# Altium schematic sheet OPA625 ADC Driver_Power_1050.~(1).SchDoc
size 558 x 431 mm; Date: Not shown in title block; ApprovedBy: Not shown in title block; CheckedBy: Not shown in title block; Author: Not shown in title block; CompanyName: Not shown in title block; Engineer: Not shown in title block; Organization: Not shown in title block; Address1: Not shown in title block; Address2: Not shown in title block; Address3: Not shown in title block; Address4: Not shown in title block; DocumentNumber: 2; Revision: Use project parameter SCH_Rev; SheetNumber: 2; SheetTotal: 8; PageSetup: Record=PageOptions¦CenterHorizontal=True¦CenterVertical=True¦PrintScale=1.00¦XCorrection=1.00¦YCorrection=1.00¦PrintKind=0¦BorderSize=5000000¦LeftOffset=0¦BottomOffset=0¦Orientation=2¦PaperLength=1000¦PaperWidth=1000¦Scale=100¦PaperSource=15¦PrintQuality=600¦MediaType=1¦DitherType=10¦PaperKind=Letter¦PrintScaleMode=1
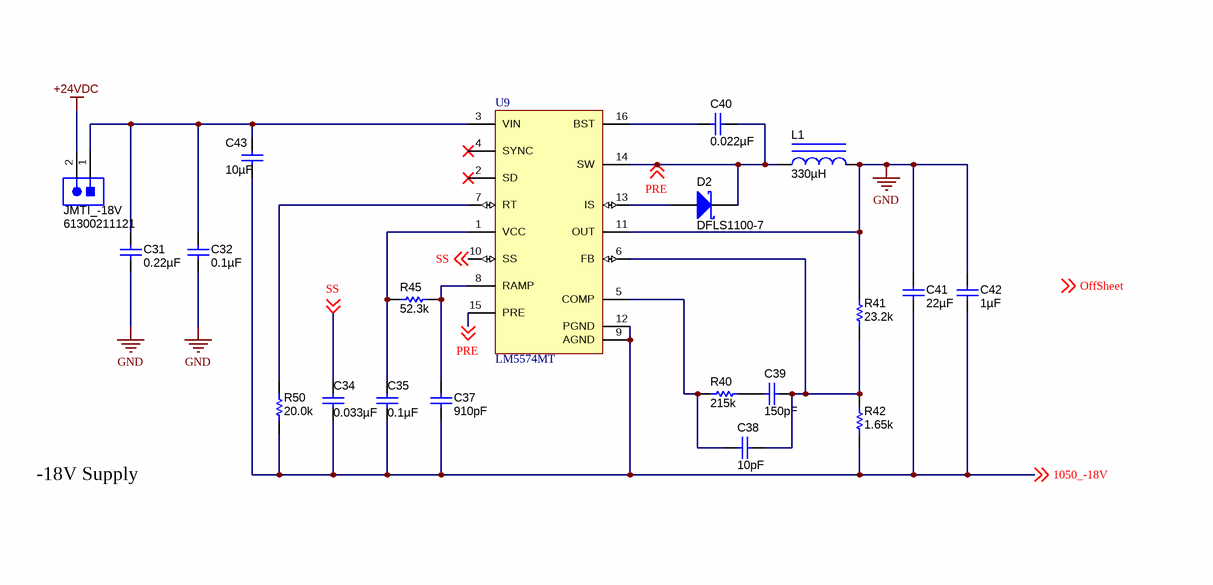
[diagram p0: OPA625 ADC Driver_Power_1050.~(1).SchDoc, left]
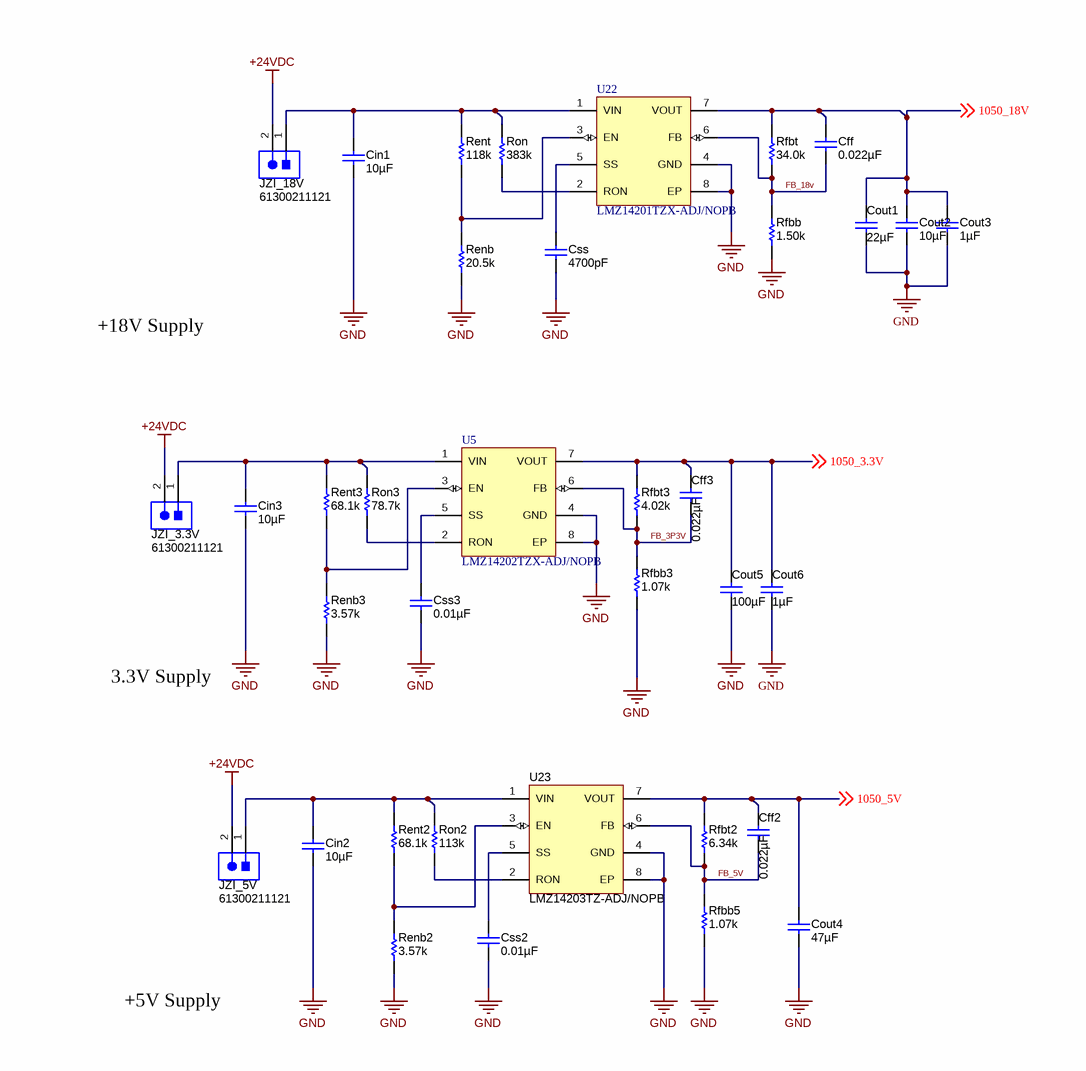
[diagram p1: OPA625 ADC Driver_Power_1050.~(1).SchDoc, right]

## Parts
C31  ValueDisplayed: 0.22µF  [0603]  (hidden comment: GCM188R71H224KA64D)
C32  ValueDisplayed: 0.1µF  [0603]  (hidden comment: C1608X7R1H104K080AA)
C34  ValueDisplayed: 0.033µF  [0603]  (hidden comment: GRM188R71H333KA61D)
C35  ValueDisplayed: 0.1µF  [0603]  (hidden comment: C1608X7R1H104K080AA)
C37  ValueDisplayed: 910pF  [0603]  (hidden comment: C0603C911J5GACTU)
C38  ValueDisplayed: 10pF  [0603]  (hidden comment: CGA3E2C0G1H100D080AA)
C39  ValueDisplayed: 150pF  [0603]  (hidden comment: GRM1885C1H151JA01D)
C40  ValueDisplayed: 0.022µF  [0603]  (hidden comment: GRM188R71H223KA01D)
C41  ValueDisplayed: 22µF  [0805_HV]  (hidden comment: C2012X5R1V226M125AC)
C42  ValueDisplayed: 1µF  [0805_HV]  (hidden comment: C2012X7S2A105K125AB)
C43  ValueDisplayed: 10µF  [1210_280]  (hidden comment: UMK325AB7106KM-T)
Cff  ValueDisplayed: 0.022µF  [0603]  (hidden comment: C1608X7R2A223K080AA)
Cff2  ValueDisplayed: 0.022µF  [0805_HV]  (hidden comment: 08055C223KAT2A)
Cff3  ValueDisplayed: 0.022µF  [0805_HV]  (hidden comment: 08055C223KAT2A)
Cin1  ValueDisplayed: 10µF  [1210_280]  (hidden comment: UMK325AB7106KM-T)
Cin2  ValueDisplayed: 10µF  [1210_280]  (hidden comment: UMK325AB7106KM-T)
Cin3  ValueDisplayed: 10µF  [1210_280]  (hidden comment: UMK325AB7106KM-T)
Cout1  ValueDisplayed: 22µF  [0805_HV]  (hidden comment: C2012JB1V226M125AC)
Cout2  ValueDisplayed: 10µF  [1210_280]  (hidden comment: UMK325AB7106KM-T)
Cout3  ValueDisplayed: 1µF  [0805_HV]  (hidden comment: C2012X7S2A105K125AB)
Cout4  ValueDisplayed: 47µF  [1206_190]  (hidden comment: C3216X5R1E476M160AC)
Cout5  ValueDisplayed: 100µF  [1210_280]  (hidden comment: C3225X6S0J107M250AC)
Cout6  ValueDisplayed: 1µF  [0603]  (hidden comment: C0603C105K3RACTU)
Css  ValueDisplayed: 4700pF  [0603]  (hidden comment: CGA3E2X7R2A472K080AA)
Css2  ValueDisplayed: 0.01µF  [0603]  (hidden comment: GRM188R70J103KA01D)
Css3  ValueDisplayed: 0.01µF  [0603]  (hidden comment: GRM188R70J103KA01D)
D2  DFLS1100-7  [PowerDI123]
JMTI_-18V  61300211121  [WURTH_61300211121]
JZI_3.3V  61300211121  [WURTH_61300211121]
JZI_5V  61300211121  [WURTH_61300211121]
JZI_18V  61300211121  [WURTH_61300211121]
L1  ValueDisplayed: 330µH  [DR73]  (hidden comment: DR73-331-R)
R40  ValueDisplayed: 215k  [0603]  (hidden comment: RT0603BRD07215KL)
R41  ValueDisplayed: 23.2k  [0603]  (hidden comment: RG1608P-2322-B-T5)
R42  ValueDisplayed: 1.65k  [0603]  (hidden comment: RG1608P-1651-B-T5)
R45  ValueDisplayed: 52.3k  [0603]  (hidden comment: RT0603BRD0752K3L)
R50  ValueDisplayed: 20.0k  [0603]  (hidden comment: RG1608P-203-B-T5)
Renb  ValueDisplayed: 20.5k  [0805_HV]  (hidden comment: CRCW080520K5FKEA)
Renb2  ValueDisplayed: 3.57k  [0603]  (hidden comment: RG1608P-3571-B-T5)
Renb3  ValueDisplayed: 3.57k  [0603]  (hidden comment: RG1608P-3571-B-T5)
Rent  value 118k  [0805_HV]  (hidden comment: RT0805BRD07118KL)
Rent2  ValueDisplayed: 68.1k  [0603]  (hidden comment: RT0603BRD0768K1L)
Rent3  ValueDisplayed: 68.1k  [0603]  (hidden comment: RT0603BRD0768K1L)
Rfbb  ValueDisplayed: 1.50k  [0603]  (hidden comment: RG1608P-152-B-T5)
Rfbb3  ValueDisplayed: 1.07k  [0805_HV]  (hidden comment: RT0805BRD071K07L)
Rfbb5  ValueDisplayed: 1.07k  [0805_HV]  (hidden comment: RT0805BRD071K07L)
Rfbt  ValueDisplayed: 34.0k  [0603]  (hidden comment: RT0603BRD0734KL)
Rfbt2  ValueDisplayed: 6.34k  [0603]  (hidden comment: CPF0603B6K34E)
Rfbt3  ValueDisplayed: 4.02k  [0603]  (hidden comment: RG1608P-4021-B-T5)
Ron  ValueDisplayed: 383k  [0603]  (hidden comment: RT0603BRD07383KL)
Ron2  ValueDisplayed: 113k  [0603]  (hidden comment: RT0603BRD07113KL)
Ron3  ValueDisplayed: 78.7k  [0603]  (hidden comment: RT0603BRD0778K7L)
U5  LMZ14202TZX-ADJ/NOPB  [TZA07A_V]
U9  LM5574MT  [MTC16_N]
U22  LMZ14201TZX-ADJ/NOPB  [TZA07A_V]
U23  LMZ14203TZ-ADJ/NOPB  [TZA07A_V]

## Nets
+24VDC: JMTI_-18V.2 JZI_3.3V.2 JZI_5V.2 JZI_18V.2
GND: C31.2 C32.2 C41.1 C42.1 Cin1.2 Cin2.2 Cin3.2 Cout1.2 Cout2.2 Cout3.2 Cout4.2 Cout5.2 Cout6.2 Css.1 Css2.2 Css3.2 L1.2 R41.2 Renb.1 Renb2.1 Renb3.1 Rfbb.1 Rfbb3.1 Rfbb5.1 U5.4(GND) U5.8(EP) U9.11(OUT) U22.4(GND) U22.8(EP) U23.4(GND) U23.8(EP)
1050_3.3V: Cff3.1 Cout5.1 Cout6.1 Rfbt3.2 U5.7(VOUT) ; off-sheet 1050_3.3V
1050_5V: Cff2.1 Cout4.1 Rfbt2.2 U23.7(VOUT) ; off-sheet 1050_5V
1050_18V: Cff.1 Cout1.1 Cout2.1 Cout3.1 Rfbt.2 U22.7(VOUT) ; off-sheet 1050_18V
1050_-18V: C34.2 C35.2 C37.2 C41.2 C42.2 C43.2 R42.1 R50.1 U9.9(AGND) U9.12(PGND) ; off-sheet 1050_-18V
FB_3P3V: Cff3.2 Rfbb3.2 Rfbt3.1 U5.6(FB)
FB_5V: Cff2.2 Rfbb5.2 Rfbt2.1 U23.6(FB)
FB_18v: Cff.2 Rfbb.2 Rfbt.1 U22.6(FB)
PRE: C40.1 D2.1(K) L1.1 U9.14(SW) U9.15(PRE) ; off-sheet PRE
SS: C34.1 U9.10(SS) ; off-sheet SS
NetC31_1: C31.1 C32.1 C43.1 JMTI_-18V.1 U9.3(VIN)
NetC35_1: C35.1 R45.1 U9.1(VCC)
NetC37_1: C37.1 R45.2 U9.8(RAMP)
NetC38_1: C38.1 C39.1 R41.1 R42.2 U9.6(FB)
NetC38_2: C38.2 R40.1 U9.5(COMP)
NetC39_2: C39.2 R40.2
NetC40_2: C40.2 U9.16(BST)
NetCin1_1: Cin1.1 JZI_18V.1 Rent.2 Ron.2 U22.1(VIN)
NetCin2_1: Cin2.1 JZI_5V.1 Rent2.2 Ron2.2 U23.1(VIN)
NetCin3_1: Cin3.1 JZI_3.3V.1 Rent3.2 Ron3.2 U5.1(VIN)
NetCss2_1: Css2.1 U23.5(SS)
NetCss3_1: Css3.1 U5.5(SS)
NetCss_2: Css.2 U22.5(SS)
NetD2_2: D2.2(A) U9.13(IS)
NetR50_2: R50.2 U9.7(RT)
NetRenb2_2: Renb2.2 Rent2.1 U23.3(EN)
NetRenb3_2: Renb3.2 Rent3.1 U5.3(EN)
NetRenb_2: Renb.2 Rent.1 U22.3(EN)
NetRon2_1: Ron2.1 U23.2(RON)
NetRon3_1: Ron3.1 U5.2(RON)
NetRon_1: Ron.1 U22.2(RON)

Not connected (* = marked no-connect by the designer): U9 2(SD)* 4(SYNC)*

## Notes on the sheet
- +18V Supply
- -18V Supply
- 3.3V Supply
- +5V Supply
- Labels drawn without touching a wire or pin: OffSheet

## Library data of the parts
C31 = GCM188R71H224KA64D: CAP, CERM, 0.22 µF, 50 V, +/- 10%, X7R, AEC-Q200 Grade 1, 0603; Manufacturer: MuRata; Polarized: N; CompType: Capacitor; Value: 0.22uF; U/M: EA; Cap_F: 0.00000022; Tolerance_%: 10; Value1: Unknown; VDC_V: 50; Value2: 50V; TaMin_C: -55; TaMax_C: 125; SizeArea_mm2: 1.28; SizeAreaWB_mm2: 4.68; SizeX_mm: 1.6; SizeY_mm: 0.8; SizeZ_mm: 1; AEC Category: Q200; AEC Qualified: Y
C32 C35 = C1608X7R1H104K080AA: CAP, CERM, 0.1 µF, 50 V, +/- 10%, X7R, 0603; Manufacturer: TDK; Polarized: N; CompType: Capacitor; Value: 0.1uF; U/M: EA; Cap_F: 0.0000001; Tolerance_%: 10; ESR_ohm: 0.0296; Value1: 0.0296 ohm; VDC_V: 50; Value2: 50V; IRMS_A: 0.97199; TaMin_C: -55; TaMax_C: 125; SizeArea_mm2: 1.28; SizeAreaWB_mm2: 4.68; SizeX_mm: 1.6; SizeY_mm: 0.8; SizeZ_mm: 1; AEC Category: Q200
C34 = GRM188R71H333KA61D: CAP, CERM, 0.033 µF, 50 V, +/- 10%, X7R, 0603; Manufacturer: MuRata; Polarized: N; CompType: Capacitor; Value: 0.033uF; U/M: EA; Cap_F: 0.000000033; Tolerance_%: 10; Value1: Unknown; VDC_V: 50; Value2: 50V; TaMin_C: -55; TaMax_C: 125; SizeArea_mm2: 1.28; SizeAreaWB_mm2: 4.68; SizeX_mm: 1.6; SizeY_mm: 0.8; SizeZ_mm: 1; AEC Category: Q200
C37 = C0603C911J5GACTU: CAP, CERM, 910 pF, 50 V, +/- 5%, C0G/NP0, 0603; Manufacturer: Kemet; Polarized: N; CompType: Capacitor; Value: 910pF; U/M: EA; Cap_F: 0.00000000091; Tolerance_%: 5; Value1: Unknown; VDC_V: 50; Value2: 50V; TaMin_C: -55; TaMax_C: 125; SizeArea_mm2: 1.28; SizeAreaWB_mm2: 4.68; SizeX_mm: 1.6; SizeY_mm: 0.8; SizeZ_mm: 1; AEC Category: Q200
C38 = CGA3E2C0G1H100D080AA: CAP, CERM, 10 pF, 50 V, +/- 5%, C0G/NP0, AEC-Q200 Grade 1, 0603; Manufacturer: TDK; Polarized: N; CompType: Capacitor; Value: 10pF; U/M: EA; Cap_F: 0.00000000001; Tolerance_%: 5; Value1: Unknown; VDC_V: 50; Value2: 50V; TaMin_C: -55; TaMax_C: 125; SizeArea_mm2: 1.28; SizeAreaWB_mm2: 4.68; SizeX_mm: 1.6; SizeY_mm: 0.8; SizeZ_mm: 1; AEC Category: Q200; AEC Qualified: Y
C39 = GRM1885C1H151JA01D: CAP, CERM, 150 pF, 50 V, +/- 5%, C0G/NP0, 0603; Manufacturer: MuRata; Polarized: N; CompType: Capacitor; Value: 150pF; U/M: EA; Cap_F: 0.00000000015; Tolerance_%: 5; Value1: Unknown; VDC_V: 50; Value2: 50V; TaMin_C: -55; TaMax_C: 125; SizeArea_mm2: 1.28; SizeAreaWB_mm2: 4.68; SizeX_mm: 1.6; SizeY_mm: 0.8; SizeZ_mm: 1; AEC Category: Q200
C40 = GRM188R71H223KA01D: CAP, CERM, 0.022 µF, 50 V, +/- 10%, X7R, 0603; Manufacturer: MuRata; Polarized: N; CompType: Capacitor; Value: 0.022uF; U/M: EA; Cap_F: 0.000000022; Tolerance_%: 10; Value1: Unknown; VDC_V: 50; Value2: 50V; TaMin_C: -55; TaMax_C: 125; SizeArea_mm2: 1.28; SizeAreaWB_mm2: 4.68; SizeX_mm: 1.6; SizeY_mm: 0.8; SizeZ_mm: 1; AEC Category: Q200
C41 = C2012X5R1V226M125AC: CAP, CERM, 22 µF, 35 V, +/- 20%, X5R, 0805; Manufacturer: TDK; Polarized: N; CompType: Capacitor; Value: 22uF; U/M: EA; Cap_F: 0.000022; Tolerance_%: 20; ESR_ohm: 0.00205; Value1: 0.00205 ohm; VDC_V: 35; Value2: 35V; IRMS_A: 4.55587; TaMin_C: -55; TaMax_C: 85; Cap_Case: 0805; SizeArea_mm2: 2.5; SizeAreaWB_mm2: 6.75; SizeX_mm: 2; SizeY_mm: 1.25; SizeZ_mm: 1.45; AEC Category: Q200
C42 Cout3 = C2012X7S2A105K125AB: CAP, CERM, 1 µF, 100 V, +/- 10%, X7S, 0805; Manufacturer: TDK; Polarized: N; CompType: Capacitor; Value: 1uF; U/M: EA; Cap_F: 0.000001; Tolerance_%: 10; ESR_ohm: 0.008255; Value1: 0.008255 ohm; VDC_V: 100; Value2: 100V; IRMS_A: 2.27442; TaMin_C: -55; TaMax_C: 125; Cap_Case: 0805; SizeArea_mm2: 2.5; SizeAreaWB_mm2: 6.75; SizeX_mm: 2; SizeY_mm: 1.25; SizeZ_mm: 1.45; AEC Category: Q200
C43 = UMK325AB7106KM-T: CAP, CERM, 10 µF, 50 V, +/- 10%, X7R, 1210; Manufacturer: Taiyo Yuden; Polarized: N; CompType: Capacitor; Value: 10uF; U/M: EA; Cap_F: 0.00001; Tolerance_%: 10; Value1: Unknown; VDC_V: 50; Value2: 50V; TaMin_C: -55; TaMax_C: 125; Cap_Case: 1210; AEC Category: Q200
Cff = C1608X7R2A223K080AA: CAP, CERM, 0.022 µF, 100 V, +/- 10%, X7R, 0603; Manufacturer: TDK; Polarized: N; CompType: Capacitor; Value: 0.022uF; U/M: EA; Cap_F: 0.000000022; Tolerance_%: 10; ESR_ohm: 0.037; Value1: 0.037 ohm; VDC_V: 100; Value2: 100V; TaMin_C: -55; TaMax_C: 125; SizeArea_mm2: 1.28; SizeAreaWB_mm2: 4.68; SizeX_mm: 1.6; SizeY_mm: 0.8; SizeZ_mm: 1; AEC Category: Q200
Cff2 Cff3 = 08055C223KAT2A: CAP, CERM, 0.022uF, 50V, +/-10%, X7R, 0805; Manufacturer: AVX; Polarized: N; CompType: Capacitor; U/M: EA; Cap_F: 0.000000022; Tolerance_%: 10; ESR_Ohm: 0.052; Value1: 0.052 ohm; VDC_V: 50; TaMin_C: -55; TaMax_C: 125; Cap_Case: 0805
Cin1-Cin3 Cout2 = UMK325AB7106KM-T: CAP, CERM, 10 µF, 50 V, +/- 10%, X7R, 1210; Manufacturer: Taiyo Yuden; Polarized: N; CompType: Capacitor; Value: 10uF; U/M: EA; Cap_F: 0.00001; Tolerance_%: 10; Value1: Unknown; VDC_V: 50; Value2: 50V; TaMin_C: -55; TaMax_C: 125; Cap_Case: 1210; SizeArea_mm2: 8; SizeAreaWB_mm2: 14.7; SizeX_mm: 3.2; SizeY_mm: 2.5; SizeZ_mm: 2.8; AEC Category: Q200
Cout1 = C2012JB1V226M125AC: CAP, CERM, 22 µF, 35 V, +/- 20%, JB, 0805; Manufacturer: TDK; Polarized: N; CompType: Capacitor; Value: 22uF; U/M: EA; Cap_F: 0.000022; Tolerance_%: 20; Value1: Unknown; VDC_V: 35; Value2: 35V; TaMin_C: -25; TaMax_C: 85; Cap_Case: 0805; SizeArea_mm2: 2.5; SizeAreaWB_mm2: 6.75; SizeX_mm: 2; SizeY_mm: 1.25; SizeZ_mm: 1.45; AEC Category: Q200
Cout4 = C3216X5R1E476M160AC: CAP, CERM, 47 µF, 25 V, +/- 20%, X5R, 1206_190; Manufacturer: TDK; Polarized: N; CompType: Capacitor; Value: 47uF; U/M: EA; Cap_F: 0.000047; Tolerance_%: 20; Value1: Unknown; VDC_V: 25; Value2: 25V; TaMin_C: -55; TaMax_C: 85; Cap_Case: 1206; AEC Category: Q200
Cout5 = C3225X6S0J107M250AC: CAP, CERM, 100 µF, 6.3 V, +/- 20%, X6S, 1210; Manufacturer: TDK; Polarized: N; CompType: Capacitor; Value: 100uF; U/M: EA; Cap_F: 0.0001; Tolerance_%: 20; ESR_ohm: 0.005496; Value1: 0.005496 ohm; VDC_V: 6.3; Value2: 6.3V; IRMS_A: 3.13651; TaMin_C: -55; TaMax_C: 105; SizeArea_mm2: 8; SizeAreaWB_mm2: 14.7; SizeX_mm: 3.2; SizeY_mm: 2.5; SizeZ_mm: 2.8; AEC Category: Q200
Cout6 = C0603C105K3RACTU: CAP, CERM, 1 µF, 25 V, +/- 10%, X7R, 0603; Manufacturer: Kemet; Polarized: N; CompType: Capacitor; Value: 1uF; U/M: EA; Cap_F: 0.000001; Tolerance_%: 10; Value1: Unknown; VDC_V: 25; Value2: 25V; TaMin_C: -55; TaMax_C: 125; SizeArea_mm2: 1.28; SizeAreaWB_mm2: 4.68; SizeX_mm: 1.6; SizeY_mm: 0.8; SizeZ_mm: 1; AEC Category: Q200
Css = CGA3E2X7R2A472K080AA: CAP, CERM, 4700 pF, 100 V, +/- 10%, X7R, AEC-Q200 Grade 1, 0603; Manufacturer: TDK; Polarized: N; CompType: Capacitor; Value: 4700pF; U/M: EA; Cap_F: 0.0000000047; Tolerance_%: 10; ESR_ohm: 0.469862; Value1: 0.469862 ohm; VDC_V: 100; Value2: 100V; IRMS_A: 0.32335; TaMin_C: -55; TaMax_C: 125; SizeArea_mm2: 1.28; SizeAreaWB_mm2: 4.68; SizeX_mm: 1.6; SizeY_mm: 0.8; SizeZ_mm: 1; AEC Category: Q200; AEC Qualified: Y
Css2 Css3 = GRM188R70J103KA01D: CAP, CERM, 0.01 µF, 6.3 V, +/- 10%, X7R, 0603; Manufacturer: MuRata; Polarized: N; CompType: Capacitor; Value: 0.01uF; U/M: EA; Cap_F: 0.00000001; Tolerance_%: 10; Value1: Unknown; VDC_V: 6.3; Value2: 6.3V; TaMin_C: -55; TaMax_C: 125; SizeArea_mm2: 1.28; SizeAreaWB_mm2: 4.68; SizeX_mm: 1.6; SizeY_mm: 0.8; SizeZ_mm: 1; AEC Category: Q200
D2 = DFLS1100-7: Diode, Schottky, 100 V, 1 A, PowerDI123; Manufacturer: Diodes Inc.; U/M: EA; Vf_V: 0.77; Value: 100V; Value1: 1A; Value2: 0.77V; Io_A: 1; Vr_V: 100; TJmax_C: 175; RJC_CperW: 7; SizeAreaWB_mm2: 13.066; SizeArea_mm2: 6.586; SizeX_mm: 3.7; SizeY_mm: 1.78; SizeZ_mm: 0.98; AEC Category: Q101
JMTI_-18V JZI_3.3V JZI_5V JZI_18V = 61300211121: Header, 2.54 mm, 2x1, Gold, TH; Manufacturer: Wurth Elektronik; SymbolCreator: a0412235
L1 = DR73-331-R: Inductor, Shielded Drum Core, Ferrite, 330 µH, 0.42 A, 1.59 ohm, SMD; Manufacturer: Coiltronics; Value: 330uH; Ind_H: 330.0E-6; Imax_A: 0.42; Irms: 0.42A @ 40C rise; Isat: 0.44A @ 30% inductance drop; DCR_ohm: 1.59; Value2: 0.42A; AEC Category: Q200
R40 = RT0603BRD07215KL: RES, 215 k, 0.1%, 0.1 W, 0603; Manufacturer: Yageo America; CompType: Resistor; Value: 215k; Res_ohm: 215000; Tolerance_%: 0.1; Value2: 0.1W; VDC_V: 75; TempCo: 25 ppm/C; SizeArea_mm2: 1.28; SizeX_mm: 1.6; SizeY_mm: 0.8; SizeZ_mm: 1; EIA_Code: E192; U/M: EA; AEC Category: Q200
R41 = RG1608P-2322-B-T5: RES, 23.2 k, 0.1%, 0.1 W, 0603; Manufacturer: Susumu Co Ltd; CompType: Resistor; Value: 23.2k; Res_ohm: 23200; Value_Code: 23k2; Tolerance_%: 0.1; Value2: 0.1W; VDC_V: 75; TempCo: 25 ppm/C; SizeArea_mm2: 1.28; SizeX_mm: 1.6; SizeY_mm: 0.8; SizeZ_mm: 1; EIA_Code: E192; U/M: EA; AEC Category: Q200
R42 = RG1608P-1651-B-T5: RES, 1.65 k, 0.1%, 0.1 W, 0603; Manufacturer: Susumu Co Ltd; CompType: Resistor; Value: 1.65k; Res_ohm: 1650; Value_Code: 1k65; Tolerance_%: 0.1; Value2: 0.1W; VDC_V: 75; TempCo: 25 ppm/C; SizeArea_mm2: 1.28; SizeX_mm: 1.6; SizeY_mm: 0.8; SizeZ_mm: 1; EIA_Code: E192; U/M: EA; AEC Category: Q200
R45 = RT0603BRD0752K3L: RES, 52.3 k, 0.1%, 0.1 W, 0603; Manufacturer: Yageo America; CompType: Resistor; Value: 52.3k; Res_ohm: 52300; Value_Code: 52k3; Tolerance_%: 0.1; Value2: 0.1W; VDC_V: 75; TempCo: 25 ppm/C; SizeArea_mm2: 1.28; SizeX_mm: 1.6; SizeY_mm: 0.8; SizeZ_mm: 1; EIA_Code: E192; U/M: EA; AEC Category: Q200
R50 = RG1608P-203-B-T5: RES, 20.0 k, 0.1%, 0.1 W, 0603; Manufacturer: Susumu Co Ltd; CompType: Resistor; Value: 20.0k; Res_ohm: 20000; Value_Code: 20k0; Tolerance_%: 0.1; Value2: 0.1W; VDC_V: 75; TempCo: 25 ppm/C; SizeArea_mm2: 1.28; SizeX_mm: 1.6; SizeY_mm: 0.8; SizeZ_mm: 1; EIA_Code: E192; U/M: EA; AEC Category: Q200
Renb = CRCW080520K5FKEA: RES, 20.5 k, 1%, 0.125 W, 0805; Manufacturer: Vishay-Dale; CompType: Resistor; Value: 20.5k; Res_ohm: 20500; Value_Code: 20k5; Tolerance_%: 1; Power_W: 0.125; Value2: 0.125W; VDC_V: 150; TempCo: 100 ppm/C; EIA_Code: E96; U/M: EA; AEC Category: Q200
Renb2 Renb3 = RG1608P-3571-B-T5: RES, 3.57 k, 0.1%, 0.1 W, 0603; Manufacturer: Susumu Co Ltd; CompType: Resistor; Value: 3.57k; Res_ohm: 3570; Value_Code: 3k57; Tolerance_%: 0.1; Value2: 0.1W; VDC_V: 75; TempCo: 25 ppm/C; SizeArea_mm2: 1.28; SizeX_mm: 1.6; SizeY_mm: 0.8; SizeZ_mm: 1; EIA_Code: E192; U/M: EA; AEC Category: Q200
Rent = RT0805BRD07118KL: RES, 118k ohm, 0.1%, 0.125W, 0805; Manufacturer: Yageo America; CompType: Resistor; Res_ohm: 118000; Tolerance_%: 0.1; Power_W: 0.125; VDC_V: 150; TempCo: 25 ppm/C; EIA_Code: E192; U/M: EA
Rent2 Rent3 = RT0603BRD0768K1L: RES, 68.1 k, 0.1%, 0.1 W, 0603; Manufacturer: Yageo America; CompType: Resistor; Value: 68.1k; Res_ohm: 68100; Value_Code: 68k1; Tolerance_%: 0.1; Value2: 0.1W; VDC_V: 75; TempCo: 25 ppm/C; SizeArea_mm2: 1.28; SizeX_mm: 1.6; SizeY_mm: 0.8; SizeZ_mm: 1; EIA_Code: E192; U/M: EA; AEC Category: Q200
Rfbb = RG1608P-152-B-T5: RES, 1.50 k, 0.1%, 0.1 W, 0603; Manufacturer: Susumu Co Ltd; CompType: Resistor; Value: 1.50k; Res_ohm: 1500; Value_Code: 1k50; Tolerance_%: 0.1; Value2: 0.1W; VDC_V: 75; TempCo: 25 ppm/C; SizeArea_mm2: 1.28; SizeX_mm: 1.6; SizeY_mm: 0.8; SizeZ_mm: 1; EIA_Code: E192; U/M: EA; AEC Category: Q200
Rfbb3 Rfbb5 = RT0805BRD071K07L: RES, 1.07 k, 0.1%, 0.125 W, 0805; Manufacturer: Yageo America; CompType: Resistor; Value: 1.07k; Res_ohm: 1070; Value_Code: 1k07; Tolerance_%: 0.1; Power_W: 0.125; Value2: 0.125W; VDC_V: 150; TempCo: 25 ppm/C; EIA_Code: E192; U/M: EA; AEC Category: Q200
Rfbt = RT0603BRD0734KL: RES, 34.0 k, 0.1%, 0.1 W, 0603; Manufacturer: Yageo America; CompType: Resistor; Value: 34.0k; Res_ohm: 34000; Value_Code: 34k0; Tolerance_%: 0.1; Value2: 0.1W; VDC_V: 75; TempCo: 25 ppm/C; SizeArea_mm2: 1.28; SizeX_mm: 1.6; SizeY_mm: 0.8; SizeZ_mm: 1; EIA_Code: E192; U/M: EA; AEC Category: Q200
Rfbt2 = CPF0603B6K34E: RES, 6.34 k, 0.1%, 0.063 W, 0603; Manufacturer: TE Connectivity; CompType: Resistor; Value: 6.34k; Res_ohm: 6340; Value_Code: 6k34; Tolerance_%: 0.1; Power_W: 0.063; Value2: 0.063W; VDC_V: 50; TempCo: 25 ppm/C; SizeArea_mm2: 1.28; SizeX_mm: 1.6; SizeY_mm: 0.8; SizeZ_mm: 1; EIA_Code: E192; U/M: EA; AEC Category: Q200
Rfbt3 = RG1608P-4021-B-T5: RES, 4.02 k, 0.1%, 0.1 W, 0603; Manufacturer: Susumu Co Ltd; CompType: Resistor; Value: 4.02k; Res_ohm: 4020; Value_Code: 4k02; Tolerance_%: 0.1; Value2: 0.1W; VDC_V: 75; TempCo: 25 ppm/C; SizeArea_mm2: 1.28; SizeX_mm: 1.6; SizeY_mm: 0.8; SizeZ_mm: 1; EIA_Code: E192; U/M: EA; AEC Category: Q200
Ron = RT0603BRD07383KL: RES, 383 k, 0.1%, 0.1 W, 0603; Manufacturer: Yageo America; CompType: Resistor; Value: 383k; Res_ohm: 383000; Tolerance_%: 0.1; Value2: 0.1W; VDC_V: 75; TempCo: 25 ppm/C; SizeArea_mm2: 1.28; SizeX_mm: 1.6; SizeY_mm: 0.8; SizeZ_mm: 1; EIA_Code: E192; U/M: EA; AEC Category: Q200
Ron2 = RT0603BRD07113KL: RES, 113 k, 0.1%, 0.1 W, 0603; Manufacturer: Yageo America; CompType: Resistor; Value: 113k; Res_ohm: 113000; Tolerance_%: 0.1; Value2: 0.1W; VDC_V: 75; TempCo: 25 ppm/C; SizeArea_mm2: 1.28; SizeX_mm: 1.6; SizeY_mm: 0.8; SizeZ_mm: 1; EIA_Code: E192; U/M: EA; AEC Category: Q200
Ron3 = RT0603BRD0778K7L: RES, 78.7 k, 0.1%, 0.1 W, 0603; Manufacturer: Yageo America; CompType: Resistor; Value: 78.7k; Res_ohm: 78700; Value_Code: 78k7; Tolerance_%: 0.1; Value2: 0.1W; VDC_V: 75; TempCo: 25 ppm/C; SizeArea_mm2: 1.28; SizeX_mm: 1.6; SizeY_mm: 0.8; SizeZ_mm: 1; EIA_Code: E192; U/M: EA; AEC Category: Q200
U5 = LMZ14202TZX-ADJ/NOPB: 2A SIMPLE SWITCHER® Power Module with 42V Maximum Input, 7 pin TO-PMOD; Manufacturer: Texas Instruments; PackageTopMarking: NSUZXYTTE#*LMZ14202*TZ-ADJ; PowerWise: Y
U9 = LM5574MT: SIMPLE SWITCHER® 75V, 0.5A Step-Down Switching Regulator, 16-pin TSSOP; Manufacturer: Texas Instruments; PackageTopMarking: NSUZXYTT*LM5574*MT; PowerWise: Y
U22 = LMZ14201TZX-ADJ/NOPB: 1A SIMPLE SWITCHER® Power Module with 42V Maximum Input, 7 pin TO-PMOD; Manufacturer: Texas Instruments; PackageTopMarking: NSUZXYTTE#*LMZ14201*TZ-ADJ; PowerWise: Y
U23 = LMZ14203TZ-ADJ/NOPB: 3A SIMPLE SWITCHER® Power Module with 42V Maximum Input Voltage, 7-pin TO-PMOD, Pb-Free; Manufacturer: Texas Instruments; PackageTopMarking: NSUZXYTTE#*LMZ14203*TZ-ADJ; PowerWise: Y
